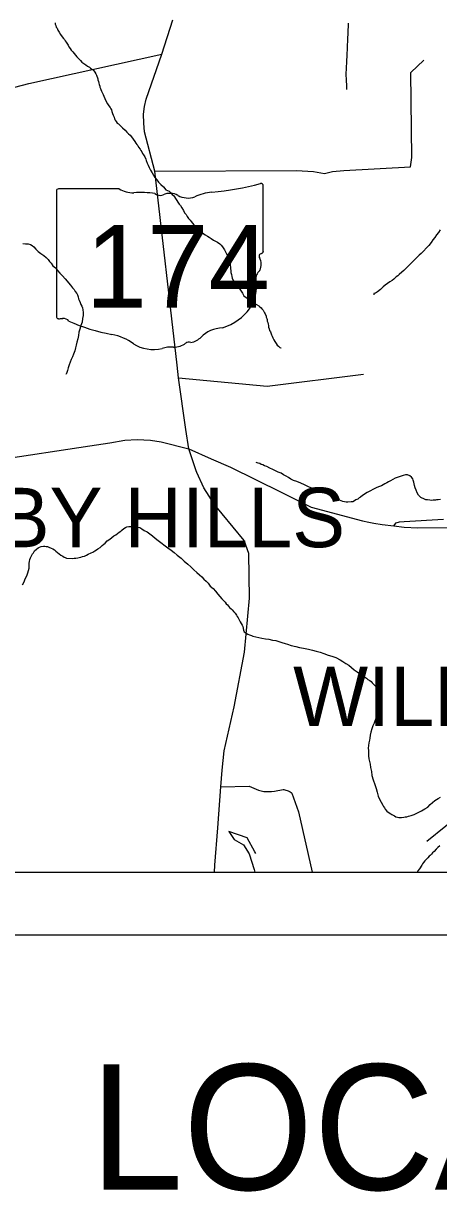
# Model space of a CAD drawing. Extents: x 0 to 44.3, y 0 to 22.
# Drawn here: x 4.321 to 4.983, y 13.591 to 15.453 of the extents above; entities that cross this region are included whole.
import ezdxf

# ---------------------------------------------------------------- set-up
doc = ezdxf.new("R2010")
doc.units = 0
for name, color, linetype in [('GM_X_City_Street', 7, 'Continuous'), ('GM_X_Corporation', 7, 'Continuous'), ('GM_X_Corporation_Text', 7, 'Continuous'), ('GM_X_County_Road', 7, 'Continuous'), ('GM_X_Major_River', 7, 'Continuous'), ('GM_X_Minor_Lake', 7, 'Continuous'), ('GM_X_Minor_River', 7, 'Continuous'), ('GM_X_State_Location', 7, 'Continuous'), ('GM_X_State_Route', 7, 'Continuous'), ('GM_X_State_Shield', 7, 'Continuous'), ('GM_X_US_Route', 7, 'Continuous'), ('SH_Data', 7, 'Continuous'), ('SH_Text', 7, 'Continuous')]:
    doc.layers.add(name, color=color, linetype=linetype)

msp = doc.modelspace()

# ---------------------------------------------------------------- linework, layer by layer
at = {"layer": 'GM_X_City_Street'}
msp.add_line((4.9644, 14.1496), (5.0597, 14.2265), dxfattribs=at)
for points in [[(4.5307, 15.2178), (4.7564, 15.2185), (4.7838, 15.2171), (4.8013, 15.2136), (4.8142, 15.2168), (4.832, 15.2187), (4.9386, 15.2242), (4.9406, 15.2394), (4.9392, 15.3747), (4.9598, 15.3947)], [(4.5685, 14.8882), (4.7099, 14.8746), (4.8637, 14.8939)], [(4.9117, 14.6522), (4.9157, 14.6569), (4.921, 14.6588), (4.9284, 14.6593), (4.9912, 14.6627)], [(4.6359, 14.2361), (4.681, 14.237), (4.6959, 14.2311), (4.7046, 14.2289), (4.71, 14.2286), (4.7168, 14.2286), (4.7217, 14.2291), (4.7353, 14.2319), (4.7363, 14.232), (4.738, 14.2314), (4.7431, 14.2296), (4.7465, 14.2281), (4.7481, 14.227), (4.749, 14.226), (4.7596, 14.1965), (4.7817, 14.1)]]:
    msp.add_lwpolyline(points, dxfattribs=at)
at = {"layer": 'GM_X_Corporation'}
for points in [[(2.1, 18.9995), (2.1, 14.1), (8.9, 14.1), (8.9, 20.9)], [(2.1, 18.9995), (2.1, 14.1), (8.9, 14.1), (8.9, 20.9)], [(2.1, 14.1), (5.9487, 14.1), (5.9448, 14.2088), (5.9233, 15.013), (5.9164, 15.3053), (5.8625, 15.324), (5.8249, 15.3328), (5.8092, 15.3398), (5.7828, 15.3485), (5.742, 15.3555), (5.7019, 15.3687), (5.6642, 15.3862), (5.6285, 15.4), (5.5927, 15.3888), (5.5557, 15.39), (5.5419, 15.3982), (5.5275, 15.412), (5.498, 15.4415), (5.4704, 15.4672)]]:
    msp.add_lwpolyline(points, dxfattribs=at)
at = {"layer": 'GM_X_County_Road'}
msp.add_lwpolyline([(3.4387, 14.7612), (3.6752, 14.9235), (3.6965, 14.9379), (3.8015, 15.0089), (3.8131, 15.0168), (3.833, 15.0303), (3.8666, 15.0529), (3.9311, 15.0966), (3.985, 15.1312), (4.0708, 15.2218), (4.0945, 15.2419), (4.1254, 15.268), (4.1424, 15.2825), (4.1646, 15.3055), (4.1695, 15.3106), (4.2026, 15.3241), (4.2355, 15.3327), (4.2599, 15.3391), (4.3293, 15.3571), (4.5415, 15.4039)], dxfattribs=at)
at = {"layer": 'GM_X_Major_River'}
msp.add_lwpolyline([(4.9854, 14.142), (4.9824, 14.1397), (4.9794, 14.1366), (4.9761, 14.1331), (4.9738, 14.1308), (4.972, 14.1289), (4.9701, 14.1269), (4.9682, 14.1254), (4.966, 14.1231), (4.9638, 14.1204), (4.9615, 14.118), (4.9593, 14.1153), (4.9578, 14.1134), (4.9564, 14.1115), (4.953, 14.1057), (4.9505, 14.1023), (4.9494, 14.1003), (4.9492, 14.1)], dxfattribs=at)
at = {"layer": 'GM_X_Minor_Lake'}
for points in [[(4.6487, 14.1651), (4.6573, 14.1523), (4.6719, 14.1435), (4.6813, 14.1292), (4.6893, 14.1043), (4.6899, 14.1)], [(4.6901, 14.1328), (4.6781, 14.155), (4.6487, 14.1651)], [(4.6917, 14.1299), (4.6901, 14.1328)]]:
    msp.add_lwpolyline(points, dxfattribs=at)
at = {"layer": 'GM_X_Minor_River'}
for points in [[(4.3713, 15.454), (4.3717, 15.4518), (4.3725, 15.4495), (4.3733, 15.4472), (4.3745, 15.4454), (4.376, 15.4424), (4.378, 15.439), (4.3803, 15.4352), (4.3827, 15.4318), (4.3846, 15.4292), (4.3862, 15.4274), (4.3877, 15.4255), (4.3893, 15.4232), (4.3913, 15.4202), (4.3924, 15.4183), (4.3936, 15.4157), (4.3952, 15.4131), (4.3971, 15.4105), (4.3995, 15.4078), (4.4018, 15.4052), (4.4041, 15.4026), (4.4061, 15.4), (4.4092, 15.3966), (4.4119, 15.394), (4.4142, 15.3914), (4.4173, 15.3892), (4.4203, 15.387), (4.423, 15.3847), (4.4261, 15.3833), (4.428, 15.3818), (4.4303, 15.3803), (4.4323, 15.3788), (4.435, 15.3755), (4.4362, 15.3728), (4.4373, 15.3706), (4.4394, 15.3649), (4.4398, 15.363), (4.4406, 15.3604), (4.4414, 15.3577), (4.4418, 15.3558)], [(4.8392, 15.4532), (4.8389, 15.4486), (4.8387, 15.4418), (4.8384, 15.4364), (4.8381, 15.4296), (4.8378, 15.4247), (4.8376, 15.4186), (4.8373, 15.4117), (4.8371, 15.4053), (4.8368, 15.4), (4.8365, 15.395), (4.8362, 15.3897), (4.8359, 15.3844), (4.8357, 15.3794), (4.8354, 15.3741), (4.8355, 15.3695), (4.8359, 15.365), (4.836, 15.3604)], [(4.4418, 15.3558), (4.4426, 15.3532), (4.443, 15.3513), (4.4438, 15.3494), (4.4442, 15.3475), (4.4454, 15.3449), (4.447, 15.3419), (4.4482, 15.3396), (4.4494, 15.337), (4.451, 15.3336), (4.4525, 15.3294), (4.4549, 15.3249), (4.4572, 15.3216), (4.4592, 15.3189), (4.4604, 15.3171), (4.4612, 15.3152), (4.462, 15.3125), (4.4628, 15.3095), (4.464, 15.3069), (4.4656, 15.3035), (4.4664, 15.3008), (4.4675, 15.2986), (4.4687, 15.2967), (4.4707, 15.2941), (4.4726, 15.293), (4.4757, 15.2896), (4.4788, 15.2866), (4.483, 15.2829), (4.4861, 15.2799), (4.4888, 15.2773), (4.4911, 15.2747), (4.4935, 15.2721), (4.4989, 15.2646), (4.5005, 15.2623), (4.5021, 15.2601), (4.5032, 15.2582), (4.5044, 15.256), (4.5071, 15.2526), (4.5083, 15.2507), (4.5099, 15.2485), (4.511, 15.2458), (4.5126, 15.2436), (4.5146, 15.2402), (4.5162, 15.2368), (4.517, 15.2345), (4.5185, 15.2304), (4.5198, 15.227), (4.5213, 15.2232), (4.5237, 15.2191), (4.5261, 15.215), (4.5284, 15.2112), (4.5307, 15.2074), (4.5335, 15.2037), (4.5366, 15.2), (4.5401, 15.1962), (4.5443, 15.1925), (4.5482, 15.188), (4.5532, 15.1854), (4.5559, 15.1828), (4.5582, 15.1806), (4.5601, 15.1787), (4.5617, 15.1765), (4.5636, 15.1739), (4.5656, 15.1709), (4.5675, 15.1682), (4.5695, 15.1652), (4.5714, 15.1626), (4.5734, 15.1592), (4.5761, 15.1547), (4.5781, 15.1513), (4.5804, 15.1483), (4.5824, 15.1453), (4.5843, 15.1423), (4.5867, 15.1393), (4.5886, 15.1371), (4.5906, 15.1345), (4.5929, 15.1319), (4.5952, 15.1292), (4.5975, 15.1266), (4.606, 15.1196), (4.6087, 15.1177), (4.611, 15.1162), (4.6145, 15.1137), (4.6172, 15.1122), (4.6202, 15.1103), (4.6241, 15.1078), (4.6275, 15.1059), (4.6306, 15.1041), (4.6345, 15.1015), (4.6364, 15.0996), (4.6387, 15.097), (4.6415, 15.0921), (4.6434, 15.0887), (4.6446, 15.0869), (4.6466, 15.0831), (4.6474, 15.0808), (4.6482, 15.0789), (4.649, 15.0771), (4.6502, 15.0741), (4.6506, 15.0703), (4.6507, 15.0676)], [(4.836, 15.3604), (4.8365, 15.3555), (4.8366, 15.3513), (4.8366, 15.3487), (4.8366, 15.3479), (4.8366, 15.3475)], [(4.9858, 15.1239), (4.9833, 15.1197), (4.9803, 15.1158), (4.9773, 15.1116), (4.9744, 15.1081), (4.9714, 15.1039), (4.9677, 15.0989), (4.9558, 15.0865), (4.9524, 15.0838), (4.9498, 15.0811), (4.9465, 15.078), (4.9427, 15.0741), (4.939, 15.0706), (4.9357, 15.0672), (4.9316, 15.0629), (4.9278, 15.0594), (4.9249, 15.0563), (4.9204, 15.0528), (4.9181, 15.0509), (4.9159, 15.0493), (4.9137, 15.047), (4.9118, 15.0455), (4.9092, 15.0431), (4.9058, 15.0412), (4.9021, 15.0384), (4.8983, 15.0357), (4.8949, 15.033), (4.8908, 15.0291), (4.886, 15.0252), (4.8826, 15.0233), (4.8807, 15.0225), (4.8803, 15.0225), (4.88, 15.0206)], [(4.3198, 15.1025), (4.3244, 15.1018), (4.3286, 15.1015), (4.3324, 15.1005), (4.3347, 15.099), (4.3374, 15.0968), (4.3405, 15.0934), (4.3444, 15.0897), (4.3486, 15.0863), (4.3532, 15.083), (4.3571, 15.0797), (4.3602, 15.0767), (4.3625, 15.0737), (4.3652, 15.0711), (4.3679, 15.0669), (4.3722, 15.0632), (4.3753, 15.0591), (4.3792, 15.055), (4.3834, 15.0505), (4.3877, 15.046), (4.3962, 15.0356), (4.3993, 15.0318), (4.4017, 15.0288), (4.4036, 15.0258), (4.406, 15.0228), (4.4071, 15.0206), (4.408, 15.0172), (4.4088, 15.0141), (4.4096, 15.0119), (4.4112, 15.0081), (4.4127, 15.0051), (4.4143, 15.0025), (4.4151, 14.9998), (4.4159, 14.9964), (4.416, 14.9922), (4.4161, 14.9877), (4.4154, 14.9827), (4.4144, 14.977), (4.4126, 14.9713), (4.4108, 14.9659), (4.4094, 14.961), (4.4087, 14.9557), (4.4077, 14.9503), (4.4063, 14.945), (4.4052, 14.9404), (4.4042, 14.9358), (4.4028, 14.9312), (4.401, 14.9259), (4.3991, 14.9217), (4.3969, 14.9171), (4.3955, 14.9132), (4.3941, 14.9087), (4.3923, 14.9041)], [(4.6507, 15.0676), (4.6511, 15.0646), (4.6515, 15.0619), (4.6519, 15.0593), (4.652, 15.0562), (4.6528, 15.0528), (4.6533, 15.0498), (4.6541, 15.0472), (4.6549, 15.0441), (4.6565, 15.0415), (4.6576, 15.0392), (4.6596, 15.0374), (4.6611, 15.0355), (4.6642, 15.0318), (4.6662, 15.0295), (4.6681, 15.0265), (4.6705, 15.0231), (4.6728, 15.0186), (4.6763, 15.016), (4.6786, 15.0138), (4.6813, 15.0116), (4.6844, 15.0097), (4.6871, 15.0079), (4.6928, 15.0049), (4.6963, 15.0027), (4.6982, 15.0012), (4.7001, 14.9998), (4.7013, 14.9979), (4.7032, 14.996), (4.7044, 14.9938), (4.7056, 14.9919), (4.7064, 14.99), (4.708, 14.9866), (4.7084, 14.9847), (4.7092, 14.9828), (4.7096, 14.9809), (4.71, 14.9787), (4.7108, 14.9764), (4.7113, 14.9734), (4.7117, 14.9715), (4.7121, 14.9688), (4.7129, 14.9662), (4.7137, 14.9636), (4.7149, 14.9613), (4.7161, 14.9583), (4.7169, 14.9564), (4.7177, 14.9545), (4.7189, 14.9519), (4.7204, 14.9489), (4.722, 14.9459), (4.724, 14.9429), (4.7259, 14.9402), (4.7278, 14.9384), (4.7298, 14.9365), (4.7309, 14.9361), (4.7313, 14.9362), (4.7317, 14.9354)], [(4.3923, 14.9041), (4.3912, 14.8999), (4.3901, 14.8968), (4.3894, 14.8949), (4.389, 14.8938), (4.3883, 14.8937)], [(4.7187, 14.7418), (4.7141, 14.744), (4.7091, 14.7466), (4.7056, 14.748), (4.7029, 14.7495), (4.7003, 14.7502), (4.698, 14.7513), (4.6957, 14.752), (4.6938, 14.7528), (4.6923, 14.7531)], [(4.9863, 14.694), (4.9829, 14.6935), (4.9803, 14.6935), (4.9784, 14.6931), (4.9765, 14.693), (4.9746, 14.693), (4.9716, 14.6926), (4.9693, 14.6929), (4.9659, 14.6936), (4.9632, 14.6939), (4.959, 14.6957), (4.9571, 14.6965), (4.9552, 14.6976), (4.9532, 14.6991), (4.9513, 14.7013), (4.9493, 14.7047), (4.9474, 14.7092), (4.9458, 14.713), (4.9449, 14.7164), (4.9445, 14.719), (4.9441, 14.7217), (4.9429, 14.7251), (4.9421, 14.727), (4.9401, 14.7296), (4.9374, 14.7318), (4.934, 14.7336), (4.9306, 14.7336), (4.9268, 14.7324), (4.9234, 14.7312), (4.9204, 14.7304), (4.9174, 14.7292), (4.914, 14.728), (4.9106, 14.726), (4.9068, 14.724), (4.9035, 14.7224), (4.9008, 14.7209), (4.8978, 14.7193), (4.8948, 14.7177), (4.8922, 14.7162), (4.8877, 14.7142), (4.8835, 14.7126), (4.8794, 14.7106), (4.8734, 14.7075), (4.8692, 14.7055), (4.8666, 14.7035), (4.8644, 14.702), (4.8621, 14.7004), (4.8588, 14.6981), (4.8569, 14.6969), (4.8543, 14.6949), (4.8513, 14.6934), (4.849, 14.6918), (4.8464, 14.6906), (4.8441, 14.6902), (4.8388, 14.6897), (4.8358, 14.6901), (4.8331, 14.6904), (4.8304, 14.6911), (4.8278, 14.6918), (4.8251, 14.6933), (4.8212, 14.6951), (4.817, 14.6977), (4.812, 14.7002), (4.8082, 14.7017), (4.8052, 14.7032), (4.8017, 14.705), (4.7975, 14.7064), (4.7933, 14.7079), (4.7887, 14.7093), (4.7841, 14.7111), (4.7795, 14.7129), (4.7746, 14.7148), (4.7692, 14.7173), (4.7638, 14.7202), (4.757, 14.7228), (4.752, 14.7246), (4.7478, 14.7268), (4.7439, 14.729), (4.7401, 14.7316), (4.7359, 14.7334), (4.732, 14.736), (4.7275, 14.7378), (4.7229, 14.74), (4.7187, 14.7418)], [(4.3195, 14.5582), (4.3213, 14.5617), (4.3228, 14.5647), (4.3238, 14.5678), (4.3257, 14.5712), (4.3268, 14.5739), (4.3278, 14.5774), (4.3289, 14.5808), (4.33, 14.5846), (4.3299, 14.5873), (4.3303, 14.5899), (4.3302, 14.5926), (4.3305, 14.5953), (4.3312, 14.5983), (4.3319, 14.601), (4.333, 14.6033), (4.3341, 14.6056), (4.3352, 14.6075), (4.3367, 14.6094), (4.3386, 14.6125), (4.3419, 14.6152), (4.3445, 14.6172), (4.3464, 14.6184), (4.3494, 14.6195), (4.3528, 14.62), (4.3551, 14.6197), (4.357, 14.6193), (4.3593, 14.619), (4.3616, 14.6183), (4.365, 14.6168), (4.3677, 14.6153), (4.3704, 14.6139), (4.3727, 14.612), (4.375, 14.6098), (4.3781, 14.6075), (4.3808, 14.6057), (4.3835, 14.6038), (4.3858, 14.6024), (4.3877, 14.6016), (4.3896, 14.6009), (4.3984, 14.6003), (4.4018, 14.6004), (4.4044, 14.6004), (4.4075, 14.6012), (4.4097, 14.6017), (4.4124, 14.6025), (4.415, 14.6033), (4.4184, 14.6041), (4.4214, 14.6053), (4.4244, 14.6069), (4.429, 14.6089), (4.4316, 14.6104), (4.435, 14.6124), (4.4376, 14.614), (4.4398, 14.6155), (4.4432, 14.6179), (4.4466, 14.621), (4.4492, 14.6229), (4.4514, 14.6248), (4.4544, 14.6283), (4.4589, 14.6311), (4.4619, 14.6334), (4.4652, 14.6361), (4.4686, 14.6381), (4.4709, 14.64), (4.4735, 14.6423), (4.4761, 14.6439), (4.478, 14.6451), (4.4813, 14.6478), (4.484, 14.6498), (4.4858, 14.6506), (4.4892, 14.6514), (4.4919, 14.6514), (4.4949, 14.6511), (4.4987, 14.6508), (4.5026, 14.6501), (4.5064, 14.6494), (4.5098, 14.6476), (4.5133, 14.6446), (4.5186, 14.6424), (4.5225, 14.6395), (4.5267, 14.6365), (4.531, 14.6328), (4.536, 14.6287), (4.5514, 14.6172), (4.5568, 14.6135), (4.5614, 14.6098), (4.566, 14.6057), (4.5726, 14.6005), (4.5776, 14.596), (4.583, 14.5912), (4.588, 14.5867), (4.593, 14.5823), (4.5977, 14.5778), (4.6019, 14.5741), (4.6054, 14.5707), (4.6089, 14.5674), (4.6123, 14.564), (4.6158, 14.561), (4.6189, 14.5561), (4.6239, 14.5521)], [(4.6239, 14.5521), (4.6274, 14.5479), (4.6309, 14.5435), (4.6344, 14.5393), (4.6375, 14.536), (4.6402, 14.533), (4.6426, 14.5304), (4.6445, 14.5281), (4.6464, 14.5263), (4.648, 14.5244), (4.6499, 14.5222), (4.6526, 14.5199), (4.6542, 14.5181), (4.6569, 14.5151), (4.6585, 14.5132), (4.6608, 14.5098), (4.662, 14.5076), (4.6635, 14.5053), (4.6647, 14.5034), (4.6667, 14.4993), (4.6686, 14.4963), (4.6698, 14.4937), (4.671, 14.4918)], [(4.671, 14.4918), (4.6719, 14.4861), (4.6731, 14.4835), (4.6761, 14.4812), (4.6788, 14.4794), (4.6819, 14.4783), (4.6846, 14.4772), (4.6872, 14.4765), (4.6918, 14.4751), (4.6964, 14.4744), (4.7013, 14.4733), (4.707, 14.4723), (4.7124, 14.4713), (4.7181, 14.4702), (4.7234, 14.4692), (4.7284, 14.4678), (4.7333, 14.4663), (4.7383, 14.4649), (4.7425, 14.4635), (4.7479, 14.4613), (4.7555, 14.4599), (4.7612, 14.4585), (4.768, 14.4571), (4.7757, 14.4557), (4.7822, 14.4539), (4.7882, 14.4525), (4.7944, 14.4507), (4.8005, 14.4486), (4.807, 14.446), (4.8131, 14.4443), (4.8196, 14.4421), (4.8261, 14.4388), (4.8307, 14.4358), (4.8353, 14.4329), (4.8399, 14.4303), (4.8445, 14.4266), (4.8488, 14.4229), (4.8534, 14.4196), (4.8653, 14.4114), (4.8684, 14.4096), (4.8707, 14.4073), (4.8738, 14.4055), (4.8757, 14.404), (4.8776, 14.4021), (4.8807, 14.3988), (4.8827, 14.3965), (4.8842, 14.3939), (4.8854, 14.3909), (4.8862, 14.3879), (4.887, 14.3852), (4.8879, 14.3822), (4.8883, 14.3773), (4.8884, 14.3735), (4.8885, 14.3693), (4.8882, 14.3655), (4.8879, 14.3613), (4.8872, 14.3575), (4.8869, 14.3545), (4.8858, 14.351), (4.8844, 14.3472), (4.8825, 14.3437), (4.8814, 14.3411), (4.8804, 14.3376), (4.8785, 14.3334), (4.8767, 14.3284), (4.8753, 14.3235), (4.8743, 14.3185), (4.8736, 14.3139), (4.8729, 14.3105), (4.8722, 14.3063), (4.8715, 14.3021), (4.8712, 14.2979), (4.8713, 14.2942), (4.8714, 14.2907), (4.8715, 14.2854), (4.8723, 14.2809), (4.8732, 14.2767), (4.874, 14.2722), (4.8749, 14.2672), (4.8761, 14.2608), (4.877, 14.2544), (4.879, 14.2472), (4.8814, 14.24), (4.8835, 14.2336), (4.8855, 14.2279), (4.8871, 14.2215), (4.8891, 14.2166), (4.8942, 14.2068), (4.8954, 14.2046), (4.8969, 14.2027), (4.8981, 14.2008), (4.9008, 14.1975), (4.9043, 14.1949), (4.907, 14.193), (4.9089, 14.1919), (4.9108, 14.1908), (4.9128, 14.1897), (4.9154, 14.1886), (4.9177, 14.1879), (4.92, 14.1875), (4.9223, 14.1872)], [(4.9223, 14.1872), (4.9242, 14.1872), (4.928, 14.1877), (4.9302, 14.1881), (4.9325, 14.1885), (4.9355, 14.1894), (4.9397, 14.1906), (4.9446, 14.1922), (4.9498, 14.1949), (4.9562, 14.1981), (4.9615, 14.2009), (4.966, 14.204), (4.9697, 14.2078), (4.9734, 14.2113), (4.9772, 14.2144), (4.9828, 14.2176), (4.9866, 14.2199)]]:
    msp.add_lwpolyline(points, dxfattribs=at)
at = {"layer": 'GM_X_State_Route'}
for points in [[(4.5662, 14.9082), (4.5307, 15.2178), (4.5141, 15.2801), (4.5129, 15.2939), (4.5126, 15.3086), (4.5142, 15.3204), (4.517, 15.3321), (4.5415, 15.4039), (4.5594, 15.4587)], [(4.5802, 14.8057), (4.5685, 14.8882), (4.5662, 14.9082)], [(4.5976, 14.7371), (4.5964, 14.7399), (4.5846, 14.7747), (4.5802, 14.8057)], [(4.626, 14.1), (4.6264, 14.1113), (4.6309, 14.171), (4.6359, 14.2361), (4.638, 14.2626), (4.6414, 14.2938), (4.6571, 14.3635), (4.6738, 14.4508), (4.6814, 14.5371), (4.6808, 14.6081), (4.6733, 14.6288), (4.6382, 14.6712), (4.626, 14.6863), (4.6089, 14.7126), (4.5976, 14.7371)]]:
    msp.add_lwpolyline(points, dxfattribs=at)
at = {"layer": 'GM_X_State_Shield'}
for p, q in [((4.3737, 15.186), (4.3737, 14.9859)), ((4.4735, 15.1895), (4.377, 15.1895)), ((4.7033, 15.0897), (4.7033, 15.1944)), ((4.7033, 15.0898), (4.7033, 15.0897))]:
    msp.add_line(p, q, dxfattribs=at)
for centre, major_axis, start_param, end_param in [((4.5859, 15.4623), (0.3495, 0), 4.814394, 5.042369), ((4.6997, 15.1949), (0.00367, 0), 6.141152, 7.989035), ((4.3775, 15.1864), (0.00382, 0), 1.712693, 3.28349), ((4.4965, 15.2127), (0.037, 0), 4.042523, 4.731795), ((4.5088, 15.0771), (0.133, 0), 1.404758, 1.657858), ((4.5389, 15.1875), (0.0107, 0), 3.836095, 5.185415), ((4.5546, 15.1644), (0.0222, 0), 0.950623, 2.079405), ((4.5833, 15.1961), (0.0267, 0), 4.081561, 5.145723), ((4.6305, 15.1283), (0.0703, 0), 1.699011, 2.107814), ((4.7025, 15.082), (0.00568, 0), 1.883978, 3.671073), ((4.6994, 15.0893), (0.00393, 0), 5.05454, 6.418171), ((4.6663, 15.0688), (0.0341, 0), 5.934695, 6.695948), ((4.7165, 15.0459), (0.0248, 0), 2.387724, 3.262537), ((4.6055, 15.0326), (0.0874, 0), 5.101752, 6.440018), ((4.3775, 14.9855), (0.00385, 0), 3.00124, 4.508301), ((4.3781, 15.0059), (0.0294, 0), 4.665946, 4.897461), ((4.3841, 14.9744), (0.0106, 0), 0.519207, 1.627899), ((4.518, 15.1542), (0.2524, 0), 4.195997, 4.488961), ((4.4427, 14.896), (0.079, 0), 0.823519, 1.323587), ((4.6423, 14.9297), (0.0479, 0), 1.647645, 2.488434), ((4.5281, 14.9734), (0.0501, 0), 4.026481, 4.996735), ((4.5571, 14.9042), (0.0412, 0), 1.495662, 1.94098), ((4.5607, 14.9584), (0.0267, 0), 4.691044, 5.507374), ((4.5849, 14.939), (0.00752, 0), 1.147584, 2.315152), ((4.5817, 14.9665), (0.0282, 0), 4.937069, 5.64225)]:
    msp.add_ellipse(centre, major_axis=major_axis, ratio=0.8, start_param=start_param, end_param=end_param, dxfattribs=at)
at = {"layer": 'GM_X_US_Route'}
for p, q in [((4.0021, 14.7154), (4.427, 14.7799)), ((4.5846, 14.7747), (4.6203, 14.7592))]:
    msp.add_line(p, q, dxfattribs=at)
for points in [[(4.427, 14.7799), (4.4586, 14.7847), (4.4828, 14.7885), (4.5022, 14.7896), (4.5235, 14.7887), (4.5407, 14.7862), (4.5846, 14.7747)], [(4.6203, 14.7592), (4.6515, 14.7457), (4.7322, 14.7057), (4.7801, 14.6819), (4.8622, 14.6603), (4.872, 14.6579), (4.8801, 14.6567), (4.8933, 14.6541), (4.9117, 14.6522), (4.9285, 14.6499), (4.9503, 14.6488), (5.4496, 14.6541)]]:
    msp.add_lwpolyline(points, dxfattribs=at)
at = {"layer": 'SH_Data'}
for p, q in [((2.1, 14.1), (8.9, 14.1)), ((2.1, 14.1), (8.9, 14.1)), ((2, 14), (9, 14))]:
    msp.add_line(p, q, dxfattribs=at)

# ---------------------------------------------------------------- texts
at = {"layer": 'GM_X_Corporation_Text'}
for p in [(3.6027, 14.6181), (4.7513, 14.3329)]:
    msp.add_text('WILLOUGHBY HILLS', height=0.094697, rotation=0, dxfattribs=at).set_placement(p)
at = {"layer": 'GM_X_State_Location'}
for s in ['s', 'r']:
    msp.add_text(s, height=0.000189, dxfattribs=at).set_placement((4.5348, 15.0727))
msp.add_text('174', height=0.000189, rotation=0, dxfattribs=at).set_placement((4.468, 15.0589))
at = {"layer": 'GM_X_State_Shield'}
msp.add_text('174', height=0.13184, dxfattribs=at).set_placement((4.4202, 15))
at = {"layer": 'SH_Text'}
msp.add_text('LOCATION MAP', height=0.2, dxfattribs=at).set_placement((4.4269, 13.5938))

doc.saveas('drawing.dxf')
